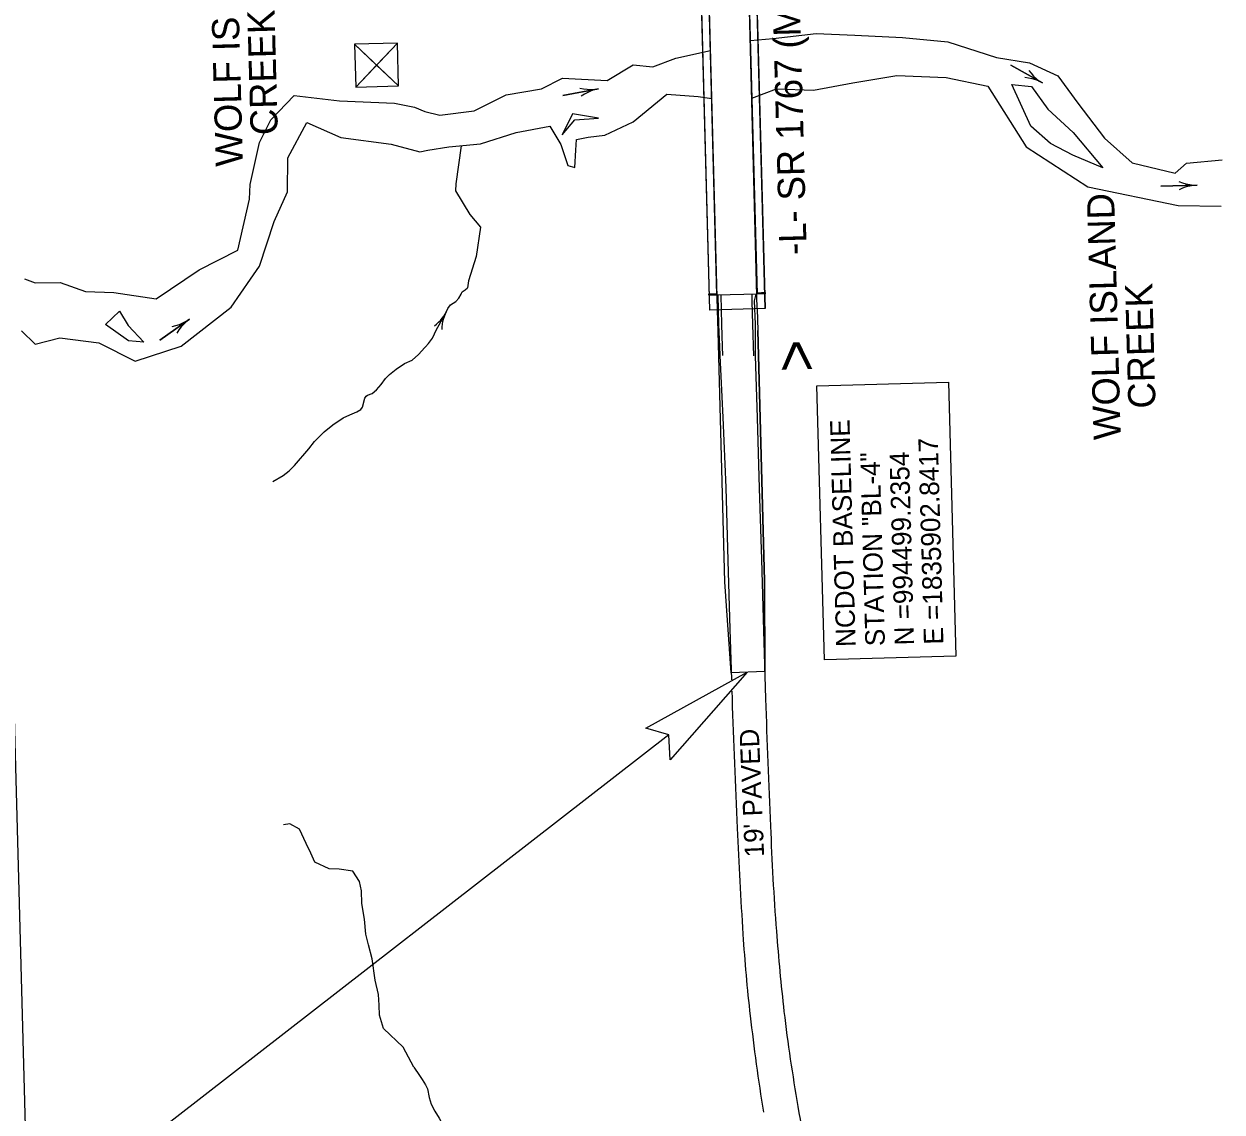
# Model space of a CAD drawing. Extents: x 1835096 to 1837089, y 993071 to 995976.
# Drawn here: x 1835495 to 1836156, y 994065 to 994665 of the extents above; entities that cross this region are included whole.
import ezdxf

# ---------------------------------------------------------------- set-up
doc = ezdxf.new("R2010")
doc.units = 0
for name, color, linetype in [('Default', 7, 'Continuous'), ('Exist Hydro River Flow Arrow CELL', 7, 'Continuous'), ('Exist Hydro Stream Flow Arrow CELL', 7, 'Continuous'), ('Exist Hydro Stream or Body of Water', 7, 'Continuous'), ('Exist Roads EOP', 7, 'Continuous'), ('Exist Roads EOP Text', 7, 'Continuous'), ('Exist Roads EOT', 7, 'Continuous'), ('Exist Structure Major Bridge WW', 7, 'Continuous'), ('Exist Structure Major Deck Tunnel Box Culvert', 7, 'Continuous'), ('Old_Level_57', 7, 'Continuous'), ('Prop EOT', 7, 'Continuous'), ('Prop Roadway Bridge', 7, 'Continuous'), ('Prop Shade Heavy', 7, 'Continuous'), ('Prop Shade Light', 7, 'Continuous'), ('Prop Terminator CELL', 7, 'Continuous'), ('Proposed Right of Way Monument PSD Text', 7, 'Continuous')]:
    doc.layers.add(name, color=color, linetype=linetype)

# ---------------------------------------------------------------- blocks, each defined once
blk = doc.blocks.new('EXIST HYDRO RIVER FLOW ARROW')
at = {"layer": 'Exist Hydro River Flow Arrow CELL'}
blk.add_line((0, 0), (0, 0), dxfattribs=at)
blk.add_lwpolyline([(0, 0.04575), (0.03775, 0.03), (0.07725, 0.01725), (0.118, 0.00775), (0.159, 0.0015), (0.2, 0), (-0.2, 0), (0.2, 0), (0.159, -0.0015), (0.118, -0.00775), (0.07725, -0.01725), (0.03775, -0.03), (0, -0.04575)], dxfattribs=at)

msp = doc.modelspace()

# ---------------------------------------------------------------- linework, layer by layer
at = {"layer": 'Default'}
for p, q in [((1835497.85, 993999.18), (1835481.16, 994610.43)), ((1835850.86, 994273.06), (1835497.85, 993999.18))]:
    msp.add_line(p, q, dxfattribs=at)
msp.add_lwpolyline([(1835936.54, 994314.41), (1835932.42, 994465.28), (1836004.97, 994467.27), (1836009.09, 994316.39)], close=True, dxfattribs=at)
at = {"layer": 'Exist Hydro Stream Flow Arrow CELL'}
msp.add_line((1835726.01, 994501.78), (1835726.01, 994501.78), dxfattribs=at)
for points in [[(1835721.72, 994498.34), (1835722.85, 994499.27), (1835723.91, 994500.33), (1835724.93, 994501.39), (1835725.85, 994502.51), (1835726.72, 994503.71), (1835727.54, 994504.97), (1835728.26, 994506.24)], [(1835725.8, 994496.28), (1835725.87, 994497.75), (1835726.1, 994499.23), (1835726.34, 994500.68), (1835726.7, 994502.09), (1835727.14, 994503.5), (1835727.67, 994504.9), (1835728.26, 994506.24)]]:
    msp.add_lwpolyline(points, dxfattribs=at)
at = {"layer": 'Exist Hydro Stream or Body of Water'}
for points in [[(1835895.72, 994655.6), (1835908.34, 994656.7), (1835932.09, 994659.37), (1835953.35, 994658.53), (1835979.55, 994657.18), (1836004.64, 994654.78), (1836031.43, 994646.2), (1836049.63, 994643.2), (1836065.15, 994636.05), (1836076.25, 994621.07), (1836090.97, 994601.72), (1836106.14, 994588.1), (1836129.97, 994582.49), (1836136.22, 994588.08), (1836155.75, 994589.8)], [(1835495.7, 994524.2), (1835501.55, 994522.03), (1835515.24, 994522.34), (1835529.27, 994517.33), (1835544.89, 994516.77), (1835568.26, 994513.2), (1835591.98, 994529.22), (1835613.23, 994540.1), (1835619.63, 994568.19), (1835620.01, 994576.2), (1835625.12, 994599.34), (1835631.42, 994611.92), (1835644.23, 994625.32), (1835669.23, 994622.31), (1835699.6, 994620.96), (1835710.65, 994618.81), (1835716.4, 994616.41), (1835724.65, 994614.46), (1835743.45, 994616.83), (1835761.13, 994625.64), (1835780.63, 994629.02), (1835792.18, 994634.89), (1835816.86, 994633.61), (1835831.17, 994642.24), (1835841.96, 994641.04), (1835854.63, 994645.87), (1835873.72, 994649.98)], [(1835896.56, 994623.88), (1835910.17, 994628.94), (1835930.5, 994628.29), (1835952.23, 994632.22), (1835976.49, 994636.35), (1836003.73, 994635.24), (1836026.64, 994630.34), (1836047.73, 994597.05), (1836081.75, 994574.93), (1836131.52, 994564.7), (1836155.24, 994564.23)], [(1836039.86, 994631.31), (1836050.76, 994630.25), (1836059.67, 994617.74), (1836073.64, 994604.83), (1836090.05, 994585.5), (1836073.59, 994592.35), (1836061.23, 994598.89), (1836050.41, 994608.37), (1836039.86, 994631.31)], [(1835494.09, 994495.65), (1835501.58, 994488.3), (1835515.23, 994491.83), (1835536.62, 994488.94), (1835556.67, 994478.82), (1835581.97, 994487.15), (1835609.65, 994508.57), (1835620.2, 994524.08), (1835625.22, 994531.19), (1835633.26, 994555.92), (1835640.68, 994572.22), (1835640.84, 994590.98), (1835651.3, 994610.45), (1835670.07, 994602.09), (1835697.68, 994598.48), (1835713.57, 994594.24), (1835717.92, 994595.07), (1835729.61, 994597.05), (1835747.02, 994598.56), (1835766.64, 994604.91), (1835785.25, 994608.41), (1835791.25, 994598.3), (1835795.23, 994586.77), (1835799.04, 994585.66), (1835799.48, 994595.16), (1835799.88, 994601.07), (1835806.36, 994602.23), (1835815.58, 994603.38), (1835831.25, 994610.75), (1835849.69, 994625.99), (1835866.94, 994624.78), (1835874.43, 994623.62)], [(1835791.98, 994603.66), (1835799.07, 994611.95), (1835812.06, 994612.84), (1835797.74, 994615.14), (1835791.98, 994603.66)], [(1835736.27, 994597.63), (1835733.41, 994576.69), (1835733.21, 994572.7), (1835741.16, 994559.79)], [(1835741.16, 994559.79), (1835747.03, 994552.71), (1835744.57, 994536.64), (1835740.38, 994523.17)], [(1835740.38, 994523.17), (1835739.88, 994519.33)], [(1835718.38, 994488.69), (1835720.51, 994491.65), (1835722.76, 994496.28), (1835727.27, 994504.46), (1835728.92, 994507.97), (1835730.56, 994509.98), (1835733.4, 994511.87), (1835735.09, 994513.58), (1835736.29, 994515.77), (1835736.47, 994516.42)], [(1835736.47, 994516.42), (1835736.87, 994517.2), (1835738.62, 994518.13), (1835739.88, 994519.33)], [(1835540.38, 994499.14), (1835548.05, 994506.4), (1835552.78, 994498.63), (1835561.4, 994489.45), (1835552.93, 994490.11), (1835540.38, 994499.14)], [(1835632.55, 994412.64), (1835638.22, 994415.99), (1835641.48, 994418.41), (1835644.52, 994421.38), (1835652.42, 994430.7), (1835655.46, 994434.74), (1835660.82, 994440.05), (1835665.67, 994443.88), (1835671.34, 994447.73), (1835675.02, 994449.4), (1835678.87, 994451.07), (1835681.06, 994452.37), (1835681.98, 994453.59), (1835683.24, 994458.51), (1835683.96, 994459.59), (1835684.74, 994460.1), (1835687.31, 994461.13), (1835689.73, 994463.14), (1835692.28, 994466.11), (1835694.59, 994469.39), (1835696.84, 994471.64), (1835700.55, 994474.46), (1835705.1, 994477.59), (1835709.38, 994479.39), (1835712.85, 994482.5), (1835716.24, 994486.38)], [(1835716.24, 994486.38), (1835716.65, 994486.85), (1835718.38, 994488.69)], [(1835710.22, 994089.87), (1835704.36, 994101.04), (1835693.57, 994111.24), (1835691.3, 994118.56), (1835691.1, 994124.1), (1835690.71, 994130.04), (1835689.04, 994137.92), (1835687.33, 994149.72), (1835685.32, 994157.35), (1835683.89, 994163.2), (1835683.16, 994171.5), (1835681.6, 994180.15), (1835681.44, 994187.12), (1835680.37, 994192.2), (1835676.55, 994197.87), (1835669.04, 994199.07), (1835663.66, 994199.31), (1835655.67, 994202.86), (1835653.46, 994207.9), (1835650.98, 994213.16), (1835647.29, 994221.03), (1835642, 994224.1), (1835638.39, 994223.51)], [(1835710.22, 994089.87), (1835713.3, 994085.39), (1835714.78, 994083.21), (1835716.73, 994080.15), (1835717.75, 994078.08), (1835718.66, 994073.27), (1835719.8, 994069.53), (1835721.82, 994065.7), (1835724.15, 994061.79), (1835726.28, 994058.11), (1835730.87, 994051.1), (1835732.91, 994047.36), (1835735.17, 994044.03), (1835736.94, 994040.49), (1835740.2, 994037.9), (1835745.02, 994037.03), (1835748.97, 994035.23), (1835751.36, 994033.82)]]:
    msp.add_lwpolyline(points, dxfattribs=at)
at = {"layer": 'Exist Roads EOP'}
for points in [[(1835877.91, 994515.25), (1835878.22, 994498.95), (1835878.68, 994486.97), (1835878.99, 994481.98), (1835880.53, 994447.85), (1835882.22, 994409.28), (1835883.27, 994369.06), (1835884.4, 994331.28), (1835885.31, 994303.36)], [(1835898.85, 994515.77), (1835897.81, 994512.06), (1835898.46, 994499.24), (1835898.36, 994481.87), (1835899.48, 994447.65), (1835900.7, 994408.99), (1835901.89, 994369.66), (1835902.98, 994330.61), (1835904.18, 994292.9)], [(1835885.51, 994297.09), (1835885.64, 994293.04)]]:
    msp.add_lwpolyline(points, dxfattribs=at)
for centre, major_axis, ratio, start_param, end_param in [((1843467.03, 994613.49), (-809.44, -7724.36), 0.976533, 4.855648, 4.864865), ((1839243.94, 994396.48), (-896.35, -3233.61), 0.995369, 5.012487, 5.033428), ((1838507.68, 994361.98), (-220.5, -2712.3), 0.963246, 4.842182, 4.86368), ((1837290.02, 994273.44), (-479.73, -1302.83), 0.996382, 5.100588, 5.142329), ((1836717.93, 994214.03), (-791.96, -241.11), 0.999196, 6.048946, 6.103473), ((1837255.37, 994278.92), (-130.52, -1367.47), 0.982283, 4.888989, 4.921418), ((1836922.61, 994250.66), (-38.19, -1039.57), 0.976726, 4.873644, 4.924434), ((1837018.9, 994257.26), (-63.22, -1157.99), 0.975191, 4.885746, 4.931935), ((1836857.23, 994226.8), (-931.25, -180.71), 0.99854, 6.259309, 6.319168)]:
    msp.add_ellipse(centre, major_axis=major_axis, ratio=ratio, start_param=start_param, end_param=end_param, dxfattribs=at)
at = {"layer": 'Exist Roads EOT'}
for points in [[(1835879.54, 994515.29), (1835879.92, 994499.07), (1835880.27, 994486.99), (1835880.34, 994481.98)], [(1835897.69, 994481.87), (1835897.17, 994499.17), (1835896.82, 994511.92), (1835896.7, 994515.7)]]:
    msp.add_lwpolyline(points, dxfattribs=at)
at = {"layer": 'Exist Structure Major Bridge WW'}
for points in [[(1835899.4, 994516.63), (1835901.83, 994516.71), (1835903.85, 994516.79), (1835903.88, 994515.99), (1835901.94, 994515.92), (1835899.42, 994515.83)], [(1835877.36, 994515.28), (1835874.87, 994515.24), (1835872.9, 994515.21), (1835872.93, 994516.01), (1835874.89, 994516.04), (1835877.34, 994516.08)]]:
    msp.add_lwpolyline(points, dxfattribs=at)
at = {"layer": 'Exist Structure Major Deck Tunnel Box Culvert'}
for points in [[(1835877.36, 994515.29), (1835872.62, 994690.49)], [(1835894.78, 994691.04), (1835899.42, 994515.82)], [(1835899.42, 994515.82), (1835877.36, 994515.29)]]:
    msp.add_lwpolyline(points, dxfattribs=at)
at = {"layer": 'Old_Level_57'}
for p, q in [((1835677.59, 994653.52), (1835701.81, 994630.58)), ((1835678.23, 994629.94), (1835701.17, 994654.16))]:
    msp.add_line(p, q, dxfattribs=at)
msp.add_lwpolyline([(1835701.81, 994630.58), (1835701.17, 994654.16), (1835677.59, 994653.52), (1835678.23, 994629.94)], close=True, dxfattribs=at)
for points in [[(1835689.7, 994642.05), (1835677.59, 994653.52), (1835678.23, 994629.94), (1835689.7, 994642.05)], [(1835689.7, 994642.05), (1835701.81, 994630.58), (1835701.17, 994654.16), (1835689.7, 994642.05)]]:
    msp.add_lwpolyline(points, dxfattribs=at)
at = {"layer": 'Prop EOT'}
for p, q in [((1835881.63, 994357.26), (1835877.93, 994495.21)), ((1835903.62, 994357.85), (1835899.92, 994495.8)), ((1835885.18, 994307.28), (1835881.63, 994357.26)), ((1835903.7, 994307.89), (1835903.62, 994357.85))]:
    msp.add_line(p, q, dxfattribs=at)
at = {"layer": 'Prop Roadway Bridge'}
for p, q in [((1835873.36, 994507.09), (1835868.28, 994697.02)), ((1835877.61, 994507.2), (1835872.53, 994697.14)), ((1835899.6, 994507.79), (1835894.52, 994697.72)), ((1835903.85, 994507.91), (1835898.77, 994697.84)), ((1835903.85, 994507.91), (1835873.36, 994507.09))]:
    msp.add_line(p, q, dxfattribs=at)
at = {"layer": 'Prop Shade Heavy'}
msp.add_lwpolyline([(1835873.36, 994507.09), (1835868.28, 994697.02), (1835898.77, 994697.84), (1835903.85, 994507.91)], close=True, dxfattribs=at)
at = {"layer": 'Prop Shade Light'}
for p, q in [((1835877.93, 994495.21), (1835877.61, 994507.2)), ((1835899.6, 994507.79), (1835899.92, 994495.8)), ((1835881.63, 994357.26), (1835877.93, 994495.21)), ((1835899.92, 994495.8), (1835903.62, 994357.85)), ((1835885.18, 994307.28), (1835881.63, 994357.26)), ((1835903.62, 994357.85), (1835903.7, 994307.89)), ((1835903.7, 994307.89), (1835885.18, 994307.28))]:
    msp.add_line(p, q, dxfattribs=at)
at = {"layer": 'Prop Terminator CELL'}
msp.add_lwpolyline([(1835838.07, 994276.74), (1835894.07, 994307.57), (1835851.56, 994259.29), (1835850.86, 994273.06)], close=True, dxfattribs=at)

# ---------------------------------------------------------------- block references
at = {"layer": 'Exist Hydro River Flow Arrow CELL', "xscale": 50}
for p, yscale, rotation in [((1836048.09, 994637.12), 50, -29.673242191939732), ((1835802.16, 994627.14), 50, 10.696902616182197), ((1836132.03, 994575.63), 50, 1.4741954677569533), ((1835578.39, 994496.23), 50.00000000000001, 35.48222211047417)]:
    msp.add_blockref('EXIST HYDRO RIVER FLOW ARROW', p, dxfattribs=dict(at, yscale=yscale, rotation=rotation))

# ---------------------------------------------------------------- texts
at = {"layer": 'Default'}
for s, p in [('-L- SR 1767 (MAYFIELD RD.)', (1835926.86, 994537.6)), ('WOLF ISLAND ', (1835616.12, 994586.42)), ('   CREEK', (1835635.78, 994586.95)), ('WOLF ISLAND ', (1836099.95, 994435.76)), ('   CREEK', (1836119.6, 994436.3))]:
    msp.add_text(s, height=15, rotation=91.56434, dxfattribs=at).set_placement(p)
at = {"layer": 'Exist Roads EOP Text'}
msp.add_text("19' PAVED", height=10.648, rotation=92.44503, dxfattribs=at).set_placement((1835903.38, 994205.89))
at = {"layer": 'Old_Level_57'}
msp.add_text('>', height=22.96, rotation=91.57854, dxfattribs=at).set_placement((1835932.49, 994473.15))
at = {"layer": 'Proposed Right of Way Monument PSD Text'}
for s, p in [('NCDOT BASELINE', (1835953.82, 994321.6)), ('E =1835902.8417 ', (1836002.19, 994322.93)), ('STATION "BL-4"', (1835969.94, 994322.04)), ('N =994499.2354 ', (1835986.07, 994322.48))]:
    msp.add_text(s, height=10.752, rotation=91.56434, dxfattribs=at).set_placement(p)

doc.saveas('drawing.dxf')
